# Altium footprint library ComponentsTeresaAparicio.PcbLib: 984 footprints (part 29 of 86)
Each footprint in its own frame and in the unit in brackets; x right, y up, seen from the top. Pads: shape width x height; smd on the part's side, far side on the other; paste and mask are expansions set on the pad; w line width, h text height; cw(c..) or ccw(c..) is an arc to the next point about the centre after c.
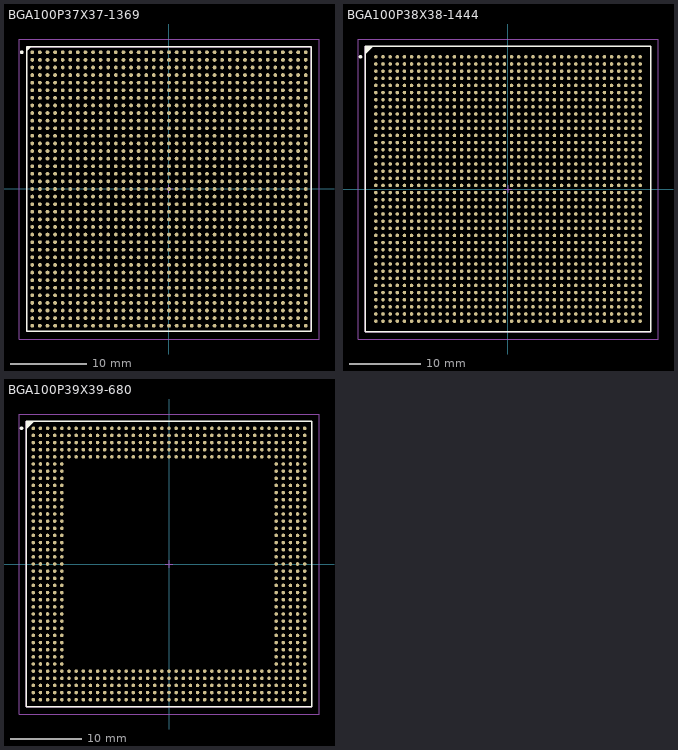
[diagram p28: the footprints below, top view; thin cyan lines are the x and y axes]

## BGA100P37X37-1369 [mm] "BGA, 1369-Leads, Body 37.5x37.5mm, Pitch 1mm"
height 3.5
pads (1369):
  round 0.5 smd: A1(-18,18) A2(-17,18) A3(-16,18) A4(-15,18) A5(-14,18) A6(-13,18) A7(-12,18) A8(-11,18) A9(-10,18) A10(-9,18) A11(-8,18) A12(-7,18) A13(-6,18) A14(-5,18) A15(-4,18) A16(-3,18) A17(-2,18) A18(-1,18) A19(0,18) A20(1,18) A21(2,18) A22(3,18) A23(4,18) A24(5,18) A25(6,18) A26(7,18) A27(8,18) A28(9,18) A29(10,18) A30(11,18) A31(12,18) A32(13,18) A33(14,18) A34(15,18) A35(16,18) A36(17,18) A37(18,18) AA1(-18,-2) AA2(-17,-2) AA3(-16,-2) AA4(-15,-2) AA5(-14,-2) AA6(-13,-2) AA7(-12,-2) AA8(-11,-2) AA9(-10,-2) AA10(-9,-2) AA11(-8,-2) AA12(-7,-2) AA13(-6,-2) AA14(-5,-2) AA15(-4,-2) AA16(-3,-2) AA17(-2,-2) AA18(-1,-2) AA19(0,-2) AA20(1,-2) AA21(2,-2) AA22(3,-2) AA23(4,-2) AA24(5,-2) AA25(6,-2) AA26(7,-2) AA27(8,-2) AA28(9,-2) AA29(10,-2) AA30(11,-2) AA31(12,-2) AA32(13,-2) AA33(14,-2) AA34(15,-2) AA35(16,-2) AA36(17,-2) AA37(18,-2) AB1(-18,-3) AB2(-17,-3) AB3(-16,-3) AB4(-15,-3) AB5(-14,-3) AB6(-13,-3) AB7(-12,-3) AB8(-11,-3) AB9(-10,-3) AB10(-9,-3) AB11(-8,-3) AB12(-7,-3) AB13(-6,-3) AB14(-5,-3) AB15(-4,-3) AB16(-3,-3) AB17(-2,-3) AB18(-1,-3) AB19(0,-3) AB20(1,-3) AB21(2,-3) AB22(3,-3) AB23(4,-3) AB24(5,-3) AB25(6,-3) AB26(7,-3) AB27(8,-3) AB28(9,-3) AB29(10,-3) AB30(11,-3) AB31(12,-3) AB32(13,-3) AB33(14,-3) AB34(15,-3) AB35(16,-3) AB36(17,-3) AB37(18,-3) AC1(-18,-4) AC2(-17,-4) AC3(-16,-4) AC4(-15,-4) AC5(-14,-4) AC6(-13,-4) AC7(-12,-4) AC8(-11,-4) AC9(-10,-4) AC10(-9,-4) AC11(-8,-4) AC12(-7,-4) AC13(-6,-4) AC14(-5,-4) AC15(-4,-4) AC16(-3,-4) AC17(-2,-4) AC18(-1,-4) AC19(0,-4) AC20(1,-4) AC21(2,-4) AC22(3,-4) AC23(4,-4) AC24(5,-4) AC25(6,-4) AC26(7,-4) AC27(8,-4) AC28(9,-4) AC29(10,-4) AC30(11,-4) AC31(12,-4) AC32(13,-4) AC33(14,-4) AC34(15,-4) AC35(16,-4) AC36(17,-4) AC37(18,-4) AD1(-18,-5) AD2(-17,-5) AD3(-16,-5) AD4(-15,-5) AD5(-14,-5) AD6(-13,-5) AD7(-12,-5) AD8(-11,-5) AD9(-10,-5) AD10(-9,-5) AD11(-8,-5) AD12(-7,-5) AD13(-6,-5) AD14(-5,-5) AD15(-4,-5) AD16(-3,-5) AD17(-2,-5) AD18(-1,-5) AD19(0,-5) AD20(1,-5) AD21(2,-5) AD22(3,-5) AD23(4,-5) AD24(5,-5) AD25(6,-5) AD26(7,-5) AD27(8,-5) AD28(9,-5) AD29(10,-5) AD30(11,-5) AD31(12,-5) AD32(13,-5) AD33(14,-5) AD34(15,-5) AD35(16,-5) AD36(17,-5) AD37(18,-5) AE1(-18,-6) AE2(-17,-6) AE3(-16,-6) AE4(-15,-6) AE5(-14,-6) AE6(-13,-6) AE7(-12,-6) AE8(-11,-6) AE9(-10,-6) AE10(-9,-6) AE11(-8,-6) AE12(-7,-6) AE13(-6,-6) AE14(-5,-6) AE15(-4,-6) AE16(-3,-6) AE17(-2,-6) AE18(-1,-6) AE19(0,-6) AE20(1,-6) AE21(2,-6) AE22(3,-6) AE23(4,-6) AE24(5,-6) AE25(6,-6) AE26(7,-6) AE27(8,-6) AE28(9,-6) AE29(10,-6) AE30(11,-6) AE31(12,-6) AE32(13,-6) AE33(14,-6) AE34(15,-6) AE35(16,-6) AE36(17,-6) AE37(18,-6) AF1(-18,-7) AF2(-17,-7) AF3(-16,-7) AF4(-15,-7) AF5(-14,-7) AF6(-13,-7) AF7(-12,-7) AF8(-11,-7) AF9(-10,-7) AF10(-9,-7) AF11(-8,-7) AF12(-7,-7) AF13(-6,-7) AF14(-5,-7) AF15(-4,-7) AF16(-3,-7) AF17(-2,-7) AF18(-1,-7) AF19(0,-7) AF20(1,-7) AF21(2,-7) AF22(3,-7) AF23(4,-7) AF24(5,-7) AF25(6,-7) AF26(7,-7) AF27(8,-7) AF28(9,-7) AF29(10,-7) AF30(11,-7) AF31(12,-7) AF32(13,-7) AF33(14,-7) AF34(15,-7) AF35(16,-7) AF36(17,-7) AF37(18,-7) AG1(-18,-8) AG2(-17,-8) AG3(-16,-8) AG4(-15,-8) AG5(-14,-8) AG6(-13,-8) AG7(-12,-8) AG8(-11,-8) AG9(-10,-8) AG10(-9,-8) AG11(-8,-8) AG12(-7,-8) AG13(-6,-8) AG14(-5,-8) AG15(-4,-8) AG16(-3,-8) AG17(-2,-8) AG18(-1,-8) AG19(0,-8) AG20(1,-8) AG21(2,-8) AG22(3,-8) AG23(4,-8) AG24(5,-8) AG25(6,-8) AG26(7,-8) AG27(8,-8) AG28(9,-8) AG29(10,-8) AG30(11,-8) AG31(12,-8) AG32(13,-8) AG33(14,-8) AG34(15,-8) AG35(16,-8) AG36(17,-8) AG37(18,-8) AH1(-18,-9) AH2(-17,-9) AH3(-16,-9) AH4(-15,-9) AH5(-14,-9) AH6(-13,-9) AH7(-12,-9) AH8(-11,-9) AH9(-10,-9) AH10(-9,-9) AH11(-8,-9) AH12(-7,-9) AH13(-6,-9) AH14(-5,-9) AH15(-4,-9) AH16(-3,-9) AH17(-2,-9) AH18(-1,-9) AH19(0,-9) AH20(1,-9) AH21(2,-9) AH22(3,-9) AH23(4,-9) AH24(5,-9) AH25(6,-9) AH26(7,-9) AH27(8,-9) AH28(9,-9) AH29(10,-9) AH30(11,-9) AH31(12,-9) AH32(13,-9) AH33(14,-9) AH34(15,-9) AH35(16,-9) AH36(17,-9) AH37(18,-9) AJ1(-18,-10) AJ2(-17,-10) AJ3(-16,-10) AJ4(-15,-10) AJ5(-14,-10) AJ6(-13,-10) AJ7(-12,-10) AJ8(-11,-10) AJ9(-10,-10) AJ10(-9,-10) AJ11(-8,-10) AJ12(-7,-10) AJ13(-6,-10) AJ14(-5,-10) AJ15(-4,-10) AJ16(-3,-10) AJ17(-2,-10) AJ18(-1,-10) AJ19(0,-10) AJ20(1,-10) AJ21(2,-10) AJ22(3,-10) AJ23(4,-10) AJ24(5,-10) AJ25(6,-10) AJ26(7,-10) AJ27(8,-10) AJ28(9,-10) AJ29(10,-10) AJ30(11,-10) AJ31(12,-10) AJ32(13,-10) AJ33(14,-10) AJ34(15,-10) AJ35(16,-10) AJ36(17,-10) AJ37(18,-10) AK1(-18,-11) AK2(-17,-11) AK3(-16,-11) AK4(-15,-11) AK5(-14,-11) AK6(-13,-11) AK7(-12,-11) AK8(-11,-11) AK9(-10,-11) AK10(-9,-11) AK11(-8,-11) AK12(-7,-11) AK13(-6,-11) AK14(-5,-11) AK15(-4,-11) AK16(-3,-11) AK17(-2,-11) AK18(-1,-11) AK19(0,-11) AK20(1,-11) AK21(2,-11) AK22(3,-11) AK23(4,-11) AK24(5,-11) AK25(6,-11) AK26(7,-11) AK27(8,-11) AK28(9,-11) AK29(10,-11) AK30(11,-11) AK31(12,-11) AK32(13,-11) AK33(14,-11) AK34(15,-11) AK35(16,-11) AK36(17,-11) AK37(18,-11) AL1(-18,-12) AL2(-17,-12) AL3(-16,-12) AL4(-15,-12) AL5(-14,-12) AL6(-13,-12) AL7(-12,-12) AL8(-11,-12) AL9(-10,-12) AL10(-9,-12) AL11(-8,-12) AL12(-7,-12) AL13(-6,-12) AL14(-5,-12) AL15(-4,-12) AL16(-3,-12) AL17(-2,-12) AL18(-1,-12) AL19(0,-12) AL20(1,-12) AL21(2,-12) AL22(3,-12) AL23(4,-12) AL24(5,-12) AL25(6,-12) AL26(7,-12) AL27(8,-12) AL28(9,-12) AL29(10,-12) AL30(11,-12) AL31(12,-12) AL32(13,-12) AL33(14,-12) AL34(15,-12) AL35(16,-12) AL36(17,-12) AL37(18,-12) AM1(-18,-13) AM2(-17,-13) AM3(-16,-13) AM4(-15,-13) AM5(-14,-13) AM6(-13,-13) AM7(-12,-13) AM8(-11,-13) AM9(-10,-13) AM10(-9,-13) AM11(-8,-13) AM12(-7,-13) AM13(-6,-13) AM14(-5,-13) AM15(-4,-13) AM16(-3,-13) AM17(-2,-13) AM18(-1,-13) AM19(0,-13) AM20(1,-13) AM21(2,-13) AM22(3,-13) AM23(4,-13) AM24(5,-13) AM25(6,-13) AM26(7,-13) AM27(8,-13) AM28(9,-13) AM29(10,-13) AM30(11,-13) AM31(12,-13) AM32(13,-13) AM33(14,-13) AM34(15,-13) AM35(16,-13) AM36(17,-13) AM37(18,-13) AN1(-18,-14) AN2(-17,-14) AN3(-16,-14) AN4(-15,-14) AN5(-14,-14) AN6(-13,-14) AN7(-12,-14) AN8(-11,-14) AN9(-10,-14) AN10(-9,-14) AN11(-8,-14) AN12(-7,-14) AN13(-6,-14) AN14(-5,-14) AN15(-4,-14) AN16(-3,-14) AN17(-2,-14) AN18(-1,-14) AN19(0,-14) AN20(1,-14) AN21(2,-14) AN22(3,-14) AN23(4,-14) AN24(5,-14) AN25(6,-14) AN26(7,-14) AN27(8,-14) AN28(9,-14) AN29(10,-14) AN30(11,-14) AN31(12,-14) AN32(13,-14) AN33(14,-14) AN34(15,-14) AN35(16,-14) AN36(17,-14) AN37(18,-14) AP1(-18,-15) AP2(-17,-15) AP3(-16,-15) AP4(-15,-15) AP5(-14,-15) AP6(-13,-15) AP7(-12,-15) AP8(-11,-15) AP9(-10,-15) AP10(-9,-15) AP11(-8,-15) AP12(-7,-15) AP13(-6,-15) AP14(-5,-15) AP15(-4,-15) AP16(-3,-15) AP17(-2,-15) AP18(-1,-15) AP19(0,-15) AP20(1,-15) AP21(2,-15) AP22(3,-15) AP23(4,-15) AP24(5,-15) AP25(6,-15) AP26(7,-15) AP27(8,-15) AP28(9,-15) AP29(10,-15) AP30(11,-15) AP31(12,-15) AP32(13,-15) AP33(14,-15) AP34(15,-15) AP35(16,-15) AP36(17,-15) AP37(18,-15) AR1(-18,-16) AR2(-17,-16) AR3(-16,-16) AR4(-15,-16) AR5(-14,-16) AR6(-13,-16) AR7(-12,-16) AR8(-11,-16) AR9(-10,-16) AR10(-9,-16) AR11(-8,-16) AR12(-7,-16) AR13(-6,-16) AR14(-5,-16) AR15(-4,-16) AR16(-3,-16) AR17(-2,-16) AR18(-1,-16) AR19(0,-16) AR20(1,-16) AR21(2,-16) AR22(3,-16) AR23(4,-16) AR24(5,-16) AR25(6,-16) AR26(7,-16) AR27(8,-16) AR28(9,-16) AR29(10,-16) AR30(11,-16) AR31(12,-16) AR32(13,-16) AR33(14,-16) AR34(15,-16) AR35(16,-16) AR36(17,-16) AR37(18,-16) AT1(-18,-17) AT2(-17,-17) AT3(-16,-17) AT4(-15,-17) AT5(-14,-17) AT6(-13,-17) AT7(-12,-17) AT8(-11,-17) AT9(-10,-17) AT10(-9,-17) AT11(-8,-17) AT12(-7,-17) AT13(-6,-17) AT14(-5,-17) AT15(-4,-17) AT16(-3,-17) AT17(-2,-17) AT18(-1,-17) AT19(0,-17) AT20(1,-17) AT21(2,-17) AT22(3,-17) AT23(4,-17) AT24(5,-17) AT25(6,-17) AT26(7,-17) AT27(8,-17) AT28(9,-17) AT29(10,-17) AT30(11,-17) AT31(12,-17) AT32(13,-17) AT33(14,-17) AT34(15,-17) AT35(16,-17) AT36(17,-17) AT37(18,-17) AU1(-18,-18) AU2(-17,-18) AU3(-16,-18) AU4(-15,-18) AU5(-14,-18) AU6(-13,-18) AU7(-12,-18) AU8(-11,-18) AU9(-10,-18) AU10(-9,-18) AU11(-8,-18) AU12(-7,-18) AU13(-6,-18) AU14(-5,-18) AU15(-4,-18) AU16(-3,-18) AU17(-2,-18) AU18(-1,-18) AU19(0,-18) AU20(1,-18) AU21(2,-18) AU22(3,-18) AU23(4,-18) AU24(5,-18) AU25(6,-18) AU26(7,-18) AU27(8,-18) AU28(9,-18) AU29(10,-18) AU30(11,-18) AU31(12,-18) AU32(13,-18) AU33(14,-18) AU34(15,-18) AU35(16,-18) AU36(17,-18) AU37(18,-18) B1(-18,17) B2(-17,17) B3(-16,17) B4(-15,17) B5(-14,17) B6(-13,17) B7(-12,17) B8(-11,17) B9(-10,17) B10(-9,17) B11(-8,17) B12(-7,17) B13(-6,17) B14(-5,17) B15(-4,17) B16(-3,17) B17(-2,17) B18(-1,17) B19(0,17) B20(1,17) B21(2,17) B22(3,17) B23(4,17) B24(5,17) B25(6,17) B26(7,17) B27(8,17) B28(9,17) B29(10,17) B30(11,17) B31(12,17) B32(13,17) B33(14,17) B34(15,17) B35(16,17) B36(17,17) B37(18,17) C1(-18,16) C2(-17,16) C3(-16,16) C4(-15,16) C5(-14,16) C6(-13,16) C7(-12,16) C8(-11,16) C9(-10,16) C10(-9,16) C11(-8,16) C12(-7,16) C13(-6,16) C14(-5,16) C15(-4,16) C16(-3,16) C17(-2,16) C18(-1,16) C19(0,16) C20(1,16) C21(2,16) C22(3,16) C23(4,16) C24(5,16) C25(6,16) C26(7,16) C27(8,16) C28(9,16) C29(10,16) C30(11,16) C31(12,16) C32(13,16) C33(14,16) C34(15,16) C35(16,16) C36(17,16) C37(18,16) D1(-18,15) D2(-17,15) D3(-16,15) D4(-15,15) D5(-14,15) D6(-13,15) D7(-12,15) D8(-11,15) D9(-10,15) D10(-9,15) D11(-8,15) D12(-7,15) D13(-6,15) D14(-5,15) D15(-4,15) D16(-3,15) D17(-2,15) D18(-1,15) D19(0,15) D20(1,15) D21(2,15) D22(3,15) D23(4,15) D24(5,15) D25(6,15) D26(7,15) D27(8,15) D28(9,15) D29(10,15) D30(11,15) D31(12,15) D32(13,15) D33(14,15) D34(15,15) D35(16,15) D36(17,15) D37(18,15) E1(-18,14) E2(-17,14) E3(-16,14) E4(-15,14) E5(-14,14) E6(-13,14) E7(-12,14) E8(-11,14) E9(-10,14) E10(-9,14) E11(-8,14) E12(-7,14) E13(-6,14) E14(-5,14) E15(-4,14) E16(-3,14) E17(-2,14) E18(-1,14) E19(0,14) E20(1,14) E21(2,14) E22(3,14) E23(4,14) E24(5,14) E25(6,14) E26(7,14) E27(8,14) E28(9,14) E29(10,14) E30(11,14) E31(12,14) E32(13,14) E33(14,14) E34(15,14) E35(16,14) E36(17,14) E37(18,14) F1(-18,13) F2(-17,13) F3(-16,13) F4(-15,13) F5(-14,13) F6(-13,13) F7(-12,13) F8(-11,13) F9(-10,13) F10(-9,13) F11(-8,13) F12(-7,13) F13(-6,13) F14(-5,13) F15(-4,13) F16(-3,13) F17(-2,13) F18(-1,13) F19(0,13) F20(1,13) F21(2,13) F22(3,13) F23(4,13) F24(5,13) F25(6,13) F26(7,13) F27(8,13) F28(9,13) F29(10,13) F30(11,13) F31(12,13) F32(13,13) F33(14,13) F34(15,13) F35(16,13) F36(17,13) F37(18,13) G1(-18,12) G2(-17,12) G3(-16,12) G4(-15,12) G5(-14,12) G6(-13,12) G7(-12,12) G8(-11,12) G9(-10,12) G10(-9,12) G11(-8,12) G12(-7,12) G13(-6,12) G14(-5,12) G15(-4,12) G16(-3,12) G17(-2,12) G18(-1,12) G19(0,12) G20(1,12) G21(2,12) G22(3,12) G23(4,12) G24(5,12) G25(6,12) G26(7,12) G27(8,12) G28(9,12) G29(10,12) G30(11,12) G31(12,12) G32(13,12) G33(14,12) G34(15,12) G35(16,12) G36(17,12) G37(18,12) H1(-18,11) H2(-17,11) H3(-16,11) H4(-15,11) H5(-14,11) H6(-13,11) H7(-12,11) H8(-11,11) H9(-10,11) H10(-9,11) H11(-8,11) H12(-7,11) H13(-6,11) H14(-5,11) H15(-4,11) H16(-3,11) H17(-2,11) H18(-1,11) H19(0,11) H20(1,11) H21(2,11) H22(3,11) H23(4,11) H24(5,11) H25(6,11) H26(7,11) H27(8,11) H28(9,11) H29(10,11) H30(11,11) H31(12,11) H32(13,11) H33(14,11) H34(15,11) H35(16,11) H36(17,11) H37(18,11) J1(-18,10) J2(-17,10) J3(-16,10) J4(-15,10) J5(-14,10) J6(-13,10) J7(-12,10) J8(-11,10) J9(-10,10) J10(-9,10) J11(-8,10) J12(-7,10) J13(-6,10) J14(-5,10) J15(-4,10) J16(-3,10) J17(-2,10) J18(-1,10) J19(0,10) J20(1,10) J21(2,10) J22(3,10) J23(4,10) J24(5,10) J25(6,10) J26(7,10) J27(8,10) J28(9,10) J29(10,10) J30(11,10) J31(12,10) J32(13,10) J33(14,10) J34(15,10) J35(16,10) J36(17,10) J37(18,10) K1(-18,9) K2(-17,9) K3(-16,9) K4(-15,9) K5(-14,9) K6(-13,9) K7(-12,9) K8(-11,9) K9(-10,9) K10(-9,9) K11(-8,9) K12(-7,9) K13(-6,9) K14(-5,9) K15(-4,9) K16(-3,9) K17(-2,9) K18(-1,9) K19(0,9) K20(1,9) K21(2,9) K22(3,9) K23(4,9) K24(5,9) K25(6,9) K26(7,9) K27(8,9) K28(9,9) K29(10,9) K30(11,9) K31(12,9) K32(13,9) K33(14,9) K34(15,9) K35(16,9) K36(17,9) K37(18,9) L1(-18,8) L2(-17,8) L3(-16,8) L4(-15,8) L5(-14,8) L6(-13,8) L7(-12,8) L8(-11,8) L9(-10,8) L10(-9,8) L11(-8,8) L12(-7,8) L13(-6,8) L14(-5,8) L15(-4,8) L16(-3,8) L17(-2,8) L18(-1,8) L19(0,8) L20(1,8) L21(2,8) L22(3,8) L23(4,8) L24(5,8) L25(6,8) L26(7,8) L27(8,8) L28(9,8) L29(10,8) L30(11,8) L31(12,8) L32(13,8) L33(14,8) L34(15,8) L35(16,8) L36(17,8) L37(18,8) M1(-18,7) M2(-17,7) M3(-16,7) M4(-15,7) M5(-14,7) M6(-13,7) M7(-12,7) M8(-11,7) M9(-10,7) M10(-9,7) M11(-8,7) M12(-7,7) M13(-6,7) M14(-5,7) M15(-4,7) M16(-3,7) M17(-2,7) M18(-1,7) M19(0,7) M20(1,7) M21(2,7) M22(3,7) M23(4,7) M24(5,7) M25(6,7) M26(7,7) M27(8,7) M28(9,7) M29(10,7) M30(11,7) M31(12,7) M32(13,7) M33(14,7) M34(15,7) M35(16,7) M36(17,7) M37(18,7) N1(-18,6) N2(-17,6) N3(-16,6) N4(-15,6) N5(-14,6) N6(-13,6) N7(-12,6) N8(-11,6) N9(-10,6) N10(-9,6) N11(-8,6) N12(-7,6) N13(-6,6) N14(-5,6) N15(-4,6) N16(-3,6) N17(-2,6) N18(-1,6) N19(0,6) N20(1,6) N21(2,6) N22(3,6) N23(4,6) N24(5,6) N25(6,6) N26(7,6) N27(8,6) N28(9,6) N29(10,6) N30(11,6) N31(12,6) N32(13,6) N33(14,6) N34(15,6) N35(16,6) N36(17,6) N37(18,6) P1(-18,5) P2(-17,5) P3(-16,5) P4(-15,5) P5(-14,5) P6(-13,5) P7(-12,5) P8(-11,5) P9(-10,5) P10(-9,5) P11(-8,5) P12(-7,5) P13(-6,5) P14(-5,5) P15(-4,5) P16(-3,5) P17(-2,5) P18(-1,5) P19(0,5) P20(1,5) P21(2,5) P22(3,5) P23(4,5) P24(5,5) P25(6,5) P26(7,5) P27(8,5) P28(9,5) P29(10,5) P30(11,5) P31(12,5) P32(13,5) P33(14,5) P34(15,5) P35(16,5) P36(17,5) P37(18,5) R1(-18,4) R2(-17,4) R3(-16,4) R4(-15,4) R5(-14,4) R6(-13,4) R7(-12,4) R8(-11,4) R9(-10,4) R10(-9,4) R11(-8,4) R12(-7,4) R13(-6,4) R14(-5,4) R15(-4,4) R16(-3,4) R17(-2,4) R18(-1,4) R19(0,4) R20(1,4) R21(2,4) R22(3,4) R23(4,4) R24(5,4) R25(6,4) R26(7,4) R27(8,4) R28(9,4) R29(10,4) R30(11,4) R31(12,4) R32(13,4) R33(14,4) R34(15,4) R35(16,4) R36(17,4) R37(18,4) T1(-18,3) T2(-17,3) T3(-16,3) T4(-15,3) T5(-14,3) T6(-13,3) T7(-12,3) T8(-11,3) T9(-10,3) T10(-9,3) T11(-8,3) T12(-7,3) T13(-6,3) T14(-5,3) T15(-4,3) T16(-3,3) T17(-2,3) T18(-1,3) T19(0,3) T20(1,3) T21(2,3) T22(3,3) T23(4,3) T24(5,3) T25(6,3) T26(7,3) T27(8,3) T28(9,3) T29(10,3) T30(11,3) T31(12,3) T32(13,3) T33(14,3) T34(15,3) T35(16,3) T36(17,3) T37(18,3) U1(-18,2) U2(-17,2) U3(-16,2) U4(-15,2) U5(-14,2) U6(-13,2) U7(-12,2) U8(-11,2) U9(-10,2) U10(-9,2) U11(-8,2) U12(-7,2) U13(-6,2) U14(-5,2) U15(-4,2) U16(-3,2) U17(-2,2) U18(-1,2) U19(0,2) U20(1,2) U21(2,2) U22(3,2) U23(4,2) U24(5,2) U25(6,2) U26(7,2) U27(8,2) U28(9,2) U29(10,2) U30(11,2) U31(12,2) U32(13,2) U33(14,2) U34(15,2) U35(16,2) U36(17,2) U37(18,2) V1(-18,1) V2(-17,1) V3(-16,1) V4(-15,1) V5(-14,1) V6(-13,1) V7(-12,1) V8(-11,1) V9(-10,1) V10(-9,1) V11(-8,1) V12(-7,1) V13(-6,1) V14(-5,1) V15(-4,1) V16(-3,1) V17(-2,1) V18(-1,1) V19(0,1) V20(1,1) V21(2,1) V22(3,1) V23(4,1) V24(5,1) V25(6,1) V26(7,1) V27(8,1) V28(9,1) V29(10,1) V30(11,1) V31(12,1) V32(13,1) V33(14,1) V34(15,1) V35(16,1) V36(17,1) V37(18,1) W1(-18,0) W2(-17,0) W3(-16,0) W4(-15,0) W5(-14,0) W6(-13,0) W7(-12,0) W8(-11,0) W9(-10,0) W10(-9,0) W11(-8,0) W12(-7,0) W13(-6,0) W14(-5,0) W15(-4,0) W16(-3,0) W17(-2,0) W18(-1,0) W19(0,0) W20(1,0) W21(2,0) W22(3,0) W23(4,0) W24(5,0) W25(6,0) W26(7,0) W27(8,0) W28(9,0) W29(10,0) W30(11,0) W31(12,0) W32(13,0) W33(14,0) W34(15,0) W35(16,0) W36(17,0) W37(18,0) Y1(-18,-1) Y2(-17,-1) Y3(-16,-1) Y4(-15,-1) Y5(-14,-1) Y6(-13,-1) Y7(-12,-1) Y8(-11,-1) Y9(-10,-1) Y10(-9,-1) Y11(-8,-1) Y12(-7,-1) Y13(-6,-1) Y14(-5,-1) Y15(-4,-1) Y16(-3,-1) Y17(-2,-1) Y18(-1,-1) Y19(0,-1) Y20(1,-1) Y21(2,-1) Y22(3,-1) Y23(4,-1) Y24(5,-1) Y25(6,-1) Y26(7,-1) Y27(8,-1) Y28(9,-1) Y29(10,-1) Y30(11,-1) Y31(12,-1) Y32(13,-1) Y33(14,-1) Y34(15,-1) Y35(16,-1) Y36(17,-1) Y37(18,-1)
Top Overlay:
  circle w0.25: c-19.4,18 r0.125
  region: -18.169,18.75 -18.75,18.169 -18.75,18.75
  lines w0.2: -18.75,18.169 -18.169,18.75 ; -18.75,-18.75 -18.75,18.75 18.75,18.75 18.75,-18.75 -18.75,-18.75
Mechanical 13:
  lines w0.1: -18.75,-18.75 -18.75,18.75 18.75,18.75 18.75,-18.75 -18.75,-18.75
Mechanical 15:
  lines w0.1: -0.5,0 0.5,0 ; 0,-0.5 0,0.5 ; -19.75,-19.75 -19.75,19.75 19.75,19.75 19.75,-19.75 -19.75,-19.75
3D body: height 0, standoff 0, extent -18.75,-18.75 18.75,18.75

## BGA100P38X38-1444 [mm] "BGA, 1444-Leads, Body 40x40mm, Pitch 1mm"
height 3.5
pads (1444):
  round 0.5 smd: A1(-18.5,18.5) A2(-17.5,18.5) A3(-16.5,18.5) A4(-15.5,18.5) A5(-14.5,18.5) A6(-13.5,18.5) A7(-12.5,18.5) A8(-11.5,18.5) A9(-10.5,18.5) A10(-9.5,18.5) A11(-8.5,18.5) A12(-7.5,18.5) A13(-6.5,18.5) A14(-5.5,18.5) A15(-4.5,18.5) A16(-3.5,18.5) A17(-2.5,18.5) A18(-1.5,18.5) A19(-0.5,18.5) A20(0.5,18.5) A21(1.5,18.5) A22(2.5,18.5) A23(3.5,18.5) A24(4.5,18.5) A25(5.5,18.5) A26(6.5,18.5) A27(7.5,18.5) A28(8.5,18.5) A29(9.5,18.5) A30(10.5,18.5) A31(11.5,18.5) A32(12.5,18.5) A33(13.5,18.5) A34(14.5,18.5) A35(15.5,18.5) A36(16.5,18.5) A37(17.5,18.5) A38(18.5,18.5) AA1(-18.5,-1.5) AA2(-17.5,-1.5) AA3(-16.5,-1.5) AA4(-15.5,-1.5) AA5(-14.5,-1.5) AA6(-13.5,-1.5) AA7(-12.5,-1.5) AA8(-11.5,-1.5) AA9(-10.5,-1.5) AA10(-9.5,-1.5) AA11(-8.5,-1.5) AA12(-7.5,-1.5) AA13(-6.5,-1.5) AA14(-5.5,-1.5) AA15(-4.5,-1.5) AA16(-3.5,-1.5) AA17(-2.5,-1.5) AA18(-1.5,-1.5) AA19(-0.5,-1.5) AA20(0.5,-1.5) AA21(1.5,-1.5) AA22(2.5,-1.5) AA23(3.5,-1.5) AA24(4.5,-1.5) AA25(5.5,-1.5) AA26(6.5,-1.5) AA27(7.5,-1.5) AA28(8.5,-1.5) AA29(9.5,-1.5) AA30(10.5,-1.5) AA31(11.5,-1.5) AA32(12.5,-1.5) AA33(13.5,-1.5) AA34(14.5,-1.5) AA35(15.5,-1.5) AA36(16.5,-1.5) AA37(17.5,-1.5) AA38(18.5,-1.5) AB1(-18.5,-2.5) AB2(-17.5,-2.5) AB3(-16.5,-2.5) AB4(-15.5,-2.5) AB5(-14.5,-2.5) AB6(-13.5,-2.5) AB7(-12.5,-2.5) AB8(-11.5,-2.5) AB9(-10.5,-2.5) AB10(-9.5,-2.5) AB11(-8.5,-2.5) AB12(-7.5,-2.5) AB13(-6.5,-2.5) AB14(-5.5,-2.5) AB15(-4.5,-2.5) AB16(-3.5,-2.5) AB17(-2.5,-2.5) AB18(-1.5,-2.5) AB19(-0.5,-2.5) AB20(0.5,-2.5) AB21(1.5,-2.5) AB22(2.5,-2.5) AB23(3.5,-2.5) AB24(4.5,-2.5) AB25(5.5,-2.5) AB26(6.5,-2.5) AB27(7.5,-2.5) AB28(8.5,-2.5) AB29(9.5,-2.5) AB30(10.5,-2.5) AB31(11.5,-2.5) AB32(12.5,-2.5) AB33(13.5,-2.5) AB34(14.5,-2.5) AB35(15.5,-2.5) AB36(16.5,-2.5) AB37(17.5,-2.5) AB38(18.5,-2.5) AC1(-18.5,-3.5) AC2(-17.5,-3.5) AC3(-16.5,-3.5) AC4(-15.5,-3.5) AC5(-14.5,-3.5) AC6(-13.5,-3.5) AC7(-12.5,-3.5) AC8(-11.5,-3.5) AC9(-10.5,-3.5) AC10(-9.5,-3.5) AC11(-8.5,-3.5) AC12(-7.5,-3.5) AC13(-6.5,-3.5) AC14(-5.5,-3.5) AC15(-4.5,-3.5) AC16(-3.5,-3.5) AC17(-2.5,-3.5) AC18(-1.5,-3.5) AC19(-0.5,-3.5) AC20(0.5,-3.5) AC21(1.5,-3.5) AC22(2.5,-3.5) AC23(3.5,-3.5) AC24(4.5,-3.5) AC25(5.5,-3.5) AC26(6.5,-3.5) AC27(7.5,-3.5) AC28(8.5,-3.5) AC29(9.5,-3.5) AC30(10.5,-3.5) AC31(11.5,-3.5) AC32(12.5,-3.5) AC33(13.5,-3.5) AC34(14.5,-3.5) AC35(15.5,-3.5) AC36(16.5,-3.5) AC37(17.5,-3.5) AC38(18.5,-3.5) AD1(-18.5,-4.5) AD2(-17.5,-4.5) AD3(-16.5,-4.5) AD4(-15.5,-4.5) AD5(-14.5,-4.5) AD6(-13.5,-4.5) AD7(-12.5,-4.5) AD8(-11.5,-4.5) AD9(-10.5,-4.5) AD10(-9.5,-4.5) AD11(-8.5,-4.5) AD12(-7.5,-4.5) AD13(-6.5,-4.5) AD14(-5.5,-4.5) AD15(-4.5,-4.5) AD16(-3.5,-4.5) AD17(-2.5,-4.5) AD18(-1.5,-4.5) AD19(-0.5,-4.5) AD20(0.5,-4.5) AD21(1.5,-4.5) AD22(2.5,-4.5) AD23(3.5,-4.5) AD24(4.5,-4.5) AD25(5.5,-4.5) AD26(6.5,-4.5) AD27(7.5,-4.5) AD28(8.5,-4.5) AD29(9.5,-4.5) AD30(10.5,-4.5) AD31(11.5,-4.5) AD32(12.5,-4.5) AD33(13.5,-4.5) AD34(14.5,-4.5) AD35(15.5,-4.5) AD36(16.5,-4.5) AD37(17.5,-4.5) AD38(18.5,-4.5) AE1(-18.5,-5.5) AE2(-17.5,-5.5) AE3(-16.5,-5.5) AE4(-15.5,-5.5) AE5(-14.5,-5.5) AE6(-13.5,-5.5) AE7(-12.5,-5.5) AE8(-11.5,-5.5) AE9(-10.5,-5.5) AE10(-9.5,-5.5) AE11(-8.5,-5.5) AE12(-7.5,-5.5) AE13(-6.5,-5.5) AE14(-5.5,-5.5) AE15(-4.5,-5.5) AE16(-3.5,-5.5) AE17(-2.5,-5.5) AE18(-1.5,-5.5) AE19(-0.5,-5.5) AE20(0.5,-5.5) AE21(1.5,-5.5) AE22(2.5,-5.5) AE23(3.5,-5.5) AE24(4.5,-5.5) AE25(5.5,-5.5) AE26(6.5,-5.5) AE27(7.5,-5.5) AE28(8.5,-5.5) AE29(9.5,-5.5) AE30(10.5,-5.5) AE31(11.5,-5.5) AE32(12.5,-5.5) AE33(13.5,-5.5) AE34(14.5,-5.5) AE35(15.5,-5.5) AE36(16.5,-5.5) AE37(17.5,-5.5) AE38(18.5,-5.5) AF1(-18.5,-6.5) AF2(-17.5,-6.5) AF3(-16.5,-6.5) AF4(-15.5,-6.5) AF5(-14.5,-6.5) AF6(-13.5,-6.5) AF7(-12.5,-6.5) AF8(-11.5,-6.5) AF9(-10.5,-6.5) AF10(-9.5,-6.5) AF11(-8.5,-6.5) AF12(-7.5,-6.5) AF13(-6.5,-6.5) AF14(-5.5,-6.5) AF15(-4.5,-6.5) AF16(-3.5,-6.5) AF17(-2.5,-6.5) AF18(-1.5,-6.5) AF19(-0.5,-6.5) AF20(0.5,-6.5) AF21(1.5,-6.5) AF22(2.5,-6.5) AF23(3.5,-6.5) AF24(4.5,-6.5) AF25(5.5,-6.5) AF26(6.5,-6.5) AF27(7.5,-6.5) AF28(8.5,-6.5) AF29(9.5,-6.5) AF30(10.5,-6.5) AF31(11.5,-6.5) AF32(12.5,-6.5) AF33(13.5,-6.5) AF34(14.5,-6.5) AF35(15.5,-6.5) AF36(16.5,-6.5) AF37(17.5,-6.5) AF38(18.5,-6.5) AG1(-18.5,-7.5) AG2(-17.5,-7.5) AG3(-16.5,-7.5) AG4(-15.5,-7.5) AG5(-14.5,-7.5) AG6(-13.5,-7.5) AG7(-12.5,-7.5) AG8(-11.5,-7.5) AG9(-10.5,-7.5) AG10(-9.5,-7.5) AG11(-8.5,-7.5) AG12(-7.5,-7.5) AG13(-6.5,-7.5) AG14(-5.5,-7.5) AG15(-4.5,-7.5) AG16(-3.5,-7.5) AG17(-2.5,-7.5) AG18(-1.5,-7.5) AG19(-0.5,-7.5) AG20(0.5,-7.5) AG21(1.5,-7.5) AG22(2.5,-7.5) AG23(3.5,-7.5) AG24(4.5,-7.5) AG25(5.5,-7.5) AG26(6.5,-7.5) AG27(7.5,-7.5) AG28(8.5,-7.5) AG29(9.5,-7.5) AG30(10.5,-7.5) AG31(11.5,-7.5) AG32(12.5,-7.5) AG33(13.5,-7.5) AG34(14.5,-7.5) AG35(15.5,-7.5) AG36(16.5,-7.5) AG37(17.5,-7.5) AG38(18.5,-7.5) AH1(-18.5,-8.5) AH2(-17.5,-8.5) AH3(-16.5,-8.5) AH4(-15.5,-8.5) AH5(-14.5,-8.5) AH6(-13.5,-8.5) AH7(-12.5,-8.5) AH8(-11.5,-8.5) AH9(-10.5,-8.5) AH10(-9.5,-8.5) AH11(-8.5,-8.5) AH12(-7.5,-8.5) AH13(-6.5,-8.5) AH14(-5.5,-8.5) AH15(-4.5,-8.5) AH16(-3.5,-8.5) AH17(-2.5,-8.5) AH18(-1.5,-8.5) AH19(-0.5,-8.5) AH20(0.5,-8.5) AH21(1.5,-8.5) AH22(2.5,-8.5) AH23(3.5,-8.5) AH24(4.5,-8.5) AH25(5.5,-8.5) AH26(6.5,-8.5) AH27(7.5,-8.5) AH28(8.5,-8.5) AH29(9.5,-8.5) AH30(10.5,-8.5) AH31(11.5,-8.5) AH32(12.5,-8.5) AH33(13.5,-8.5) AH34(14.5,-8.5) AH35(15.5,-8.5) AH36(16.5,-8.5) AH37(17.5,-8.5) AH38(18.5,-8.5) AJ1(-18.5,-9.5) AJ2(-17.5,-9.5) AJ3(-16.5,-9.5) AJ4(-15.5,-9.5) AJ5(-14.5,-9.5) AJ6(-13.5,-9.5) AJ7(-12.5,-9.5) AJ8(-11.5,-9.5) AJ9(-10.5,-9.5) AJ10(-9.5,-9.5) AJ11(-8.5,-9.5) AJ12(-7.5,-9.5) AJ13(-6.5,-9.5) AJ14(-5.5,-9.5) AJ15(-4.5,-9.5) AJ16(-3.5,-9.5) AJ17(-2.5,-9.5) AJ18(-1.5,-9.5) AJ19(-0.5,-9.5) AJ20(0.5,-9.5) AJ21(1.5,-9.5) AJ22(2.5,-9.5) AJ23(3.5,-9.5) AJ24(4.5,-9.5) AJ25(5.5,-9.5) AJ26(6.5,-9.5) AJ27(7.5,-9.5) AJ28(8.5,-9.5) AJ29(9.5,-9.5) AJ30(10.5,-9.5) AJ31(11.5,-9.5) AJ32(12.5,-9.5) AJ33(13.5,-9.5) AJ34(14.5,-9.5) AJ35(15.5,-9.5) AJ36(16.5,-9.5) AJ37(17.5,-9.5) AJ38(18.5,-9.5) AK1(-18.5,-10.5) AK2(-17.5,-10.5) AK3(-16.5,-10.5) AK4(-15.5,-10.5) AK5(-14.5,-10.5) AK6(-13.5,-10.5) AK7(-12.5,-10.5) AK8(-11.5,-10.5) AK9(-10.5,-10.5) AK10(-9.5,-10.5) AK11(-8.5,-10.5) AK12(-7.5,-10.5) AK13(-6.5,-10.5) AK14(-5.5,-10.5) AK15(-4.5,-10.5) AK16(-3.5,-10.5) AK17(-2.5,-10.5) AK18(-1.5,-10.5) AK19(-0.5,-10.5) AK20(0.5,-10.5) AK21(1.5,-10.5) AK22(2.5,-10.5) AK23(3.5,-10.5) AK24(4.5,-10.5) AK25(5.5,-10.5) AK26(6.5,-10.5) AK27(7.5,-10.5) AK28(8.5,-10.5) AK29(9.5,-10.5) AK30(10.5,-10.5) AK31(11.5,-10.5) AK32(12.5,-10.5) AK33(13.5,-10.5) AK34(14.5,-10.5) AK35(15.5,-10.5) AK36(16.5,-10.5) AK37(17.5,-10.5) AK38(18.5,-10.5) AL1(-18.5,-11.5) AL2(-17.5,-11.5) AL3(-16.5,-11.5) AL4(-15.5,-11.5) AL5(-14.5,-11.5) AL6(-13.5,-11.5) AL7(-12.5,-11.5) AL8(-11.5,-11.5) AL9(-10.5,-11.5) AL10(-9.5,-11.5) AL11(-8.5,-11.5) AL12(-7.5,-11.5) AL13(-6.5,-11.5) AL14(-5.5,-11.5) AL15(-4.5,-11.5) AL16(-3.5,-11.5) AL17(-2.5,-11.5) AL18(-1.5,-11.5) AL19(-0.5,-11.5) AL20(0.5,-11.5) AL21(1.5,-11.5) AL22(2.5,-11.5) AL23(3.5,-11.5) AL24(4.5,-11.5) AL25(5.5,-11.5) AL26(6.5,-11.5) AL27(7.5,-11.5) AL28(8.5,-11.5) AL29(9.5,-11.5) AL30(10.5,-11.5) AL31(11.5,-11.5) AL32(12.5,-11.5) AL33(13.5,-11.5) AL34(14.5,-11.5) AL35(15.5,-11.5) AL36(16.5,-11.5) AL37(17.5,-11.5) AL38(18.5,-11.5) AM1(-18.5,-12.5) AM2(-17.5,-12.5) AM3(-16.5,-12.5) AM4(-15.5,-12.5) AM5(-14.5,-12.5) AM6(-13.5,-12.5) AM7(-12.5,-12.5) AM8(-11.5,-12.5) AM9(-10.5,-12.5) AM10(-9.5,-12.5) AM11(-8.5,-12.5) AM12(-7.5,-12.5) AM13(-6.5,-12.5) AM14(-5.5,-12.5) AM15(-4.5,-12.5) AM16(-3.5,-12.5) AM17(-2.5,-12.5) AM18(-1.5,-12.5) AM19(-0.5,-12.5) AM20(0.5,-12.5) AM21(1.5,-12.5) AM22(2.5,-12.5) AM23(3.5,-12.5) AM24(4.5,-12.5) AM25(5.5,-12.5) AM26(6.5,-12.5) AM27(7.5,-12.5) AM28(8.5,-12.5) AM29(9.5,-12.5) AM30(10.5,-12.5) AM31(11.5,-12.5) AM32(12.5,-12.5) AM33(13.5,-12.5) AM34(14.5,-12.5) AM35(15.5,-12.5) AM36(16.5,-12.5) AM37(17.5,-12.5) AM38(18.5,-12.5) AN1(-18.5,-13.5) AN2(-17.5,-13.5) AN3(-16.5,-13.5) AN4(-15.5,-13.5) AN5(-14.5,-13.5) AN6(-13.5,-13.5) AN7(-12.5,-13.5) AN8(-11.5,-13.5) AN9(-10.5,-13.5) AN10(-9.5,-13.5) AN11(-8.5,-13.5) AN12(-7.5,-13.5) AN13(-6.5,-13.5) AN14(-5.5,-13.5) AN15(-4.5,-13.5) AN16(-3.5,-13.5) AN17(-2.5,-13.5) AN18(-1.5,-13.5) AN19(-0.5,-13.5) AN20(0.5,-13.5) AN21(1.5,-13.5) AN22(2.5,-13.5) AN23(3.5,-13.5) AN24(4.5,-13.5) AN25(5.5,-13.5) AN26(6.5,-13.5) AN27(7.5,-13.5) AN28(8.5,-13.5) AN29(9.5,-13.5) AN30(10.5,-13.5) AN31(11.5,-13.5) AN32(12.5,-13.5) AN33(13.5,-13.5) AN34(14.5,-13.5) AN35(15.5,-13.5) AN36(16.5,-13.5) AN37(17.5,-13.5) AN38(18.5,-13.5) AP1(-18.5,-14.5) AP2(-17.5,-14.5) AP3(-16.5,-14.5) AP4(-15.5,-14.5) AP5(-14.5,-14.5) AP6(-13.5,-14.5) AP7(-12.5,-14.5) AP8(-11.5,-14.5) AP9(-10.5,-14.5) AP10(-9.5,-14.5) AP11(-8.5,-14.5) AP12(-7.5,-14.5) AP13(-6.5,-14.5) AP14(-5.5,-14.5) AP15(-4.5,-14.5) AP16(-3.5,-14.5) AP17(-2.5,-14.5) AP18(-1.5,-14.5) AP19(-0.5,-14.5) AP20(0.5,-14.5) AP21(1.5,-14.5) AP22(2.5,-14.5) AP23(3.5,-14.5) AP24(4.5,-14.5) AP25(5.5,-14.5) AP26(6.5,-14.5) AP27(7.5,-14.5) AP28(8.5,-14.5) AP29(9.5,-14.5) AP30(10.5,-14.5) AP31(11.5,-14.5) AP32(12.5,-14.5) AP33(13.5,-14.5) AP34(14.5,-14.5) AP35(15.5,-14.5) AP36(16.5,-14.5) AP37(17.5,-14.5) AP38(18.5,-14.5) AR1(-18.5,-15.5) AR2(-17.5,-15.5) AR3(-16.5,-15.5) AR4(-15.5,-15.5) AR5(-14.5,-15.5) AR6(-13.5,-15.5) AR7(-12.5,-15.5) AR8(-11.5,-15.5) AR9(-10.5,-15.5) AR10(-9.5,-15.5) AR11(-8.5,-15.5) AR12(-7.5,-15.5) AR13(-6.5,-15.5) AR14(-5.5,-15.5) AR15(-4.5,-15.5) AR16(-3.5,-15.5) AR17(-2.5,-15.5) AR18(-1.5,-15.5) AR19(-0.5,-15.5) AR20(0.5,-15.5) AR21(1.5,-15.5) AR22(2.5,-15.5) AR23(3.5,-15.5) AR24(4.5,-15.5) AR25(5.5,-15.5) AR26(6.5,-15.5) AR27(7.5,-15.5) AR28(8.5,-15.5) AR29(9.5,-15.5) AR30(10.5,-15.5) AR31(11.5,-15.5) AR32(12.5,-15.5) AR33(13.5,-15.5) AR34(14.5,-15.5) AR35(15.5,-15.5) AR36(16.5,-15.5) AR37(17.5,-15.5) AR38(18.5,-15.5) AT1(-18.5,-16.5) AT2(-17.5,-16.5) AT3(-16.5,-16.5) AT4(-15.5,-16.5) AT5(-14.5,-16.5) AT6(-13.5,-16.5) AT7(-12.5,-16.5) AT8(-11.5,-16.5) AT9(-10.5,-16.5) AT10(-9.5,-16.5) AT11(-8.5,-16.5) AT12(-7.5,-16.5) AT13(-6.5,-16.5) AT14(-5.5,-16.5) AT15(-4.5,-16.5) AT16(-3.5,-16.5) AT17(-2.5,-16.5) AT18(-1.5,-16.5) AT19(-0.5,-16.5) AT20(0.5,-16.5) AT21(1.5,-16.5) AT22(2.5,-16.5) AT23(3.5,-16.5) AT24(4.5,-16.5) AT25(5.5,-16.5) AT26(6.5,-16.5) AT27(7.5,-16.5) AT28(8.5,-16.5) AT29(9.5,-16.5) AT30(10.5,-16.5) AT31(11.5,-16.5) AT32(12.5,-16.5) AT33(13.5,-16.5) AT34(14.5,-16.5) AT35(15.5,-16.5) AT36(16.5,-16.5) AT37(17.5,-16.5) AT38(18.5,-16.5) AU1(-18.5,-17.5) AU2(-17.5,-17.5) AU3(-16.5,-17.5) AU4(-15.5,-17.5) AU5(-14.5,-17.5) AU6(-13.5,-17.5) AU7(-12.5,-17.5) AU8(-11.5,-17.5) AU9(-10.5,-17.5) AU10(-9.5,-17.5) AU11(-8.5,-17.5) AU12(-7.5,-17.5) AU13(-6.5,-17.5) AU14(-5.5,-17.5) AU15(-4.5,-17.5) AU16(-3.5,-17.5) AU17(-2.5,-17.5) AU18(-1.5,-17.5) AU19(-0.5,-17.5) AU20(0.5,-17.5) AU21(1.5,-17.5) AU22(2.5,-17.5) AU23(3.5,-17.5) AU24(4.5,-17.5) AU25(5.5,-17.5) AU26(6.5,-17.5) AU27(7.5,-17.5) AU28(8.5,-17.5) AU29(9.5,-17.5) AU30(10.5,-17.5) AU31(11.5,-17.5) AU32(12.5,-17.5) AU33(13.5,-17.5) AU34(14.5,-17.5) AU35(15.5,-17.5) AU36(16.5,-17.5) AU37(17.5,-17.5) AU38(18.5,-17.5) AV1(-18.5,-18.5) AV2(-17.5,-18.5) AV3(-16.5,-18.5) AV4(-15.5,-18.5) AV5(-14.5,-18.5) AV6(-13.5,-18.5) AV7(-12.5,-18.5) AV8(-11.5,-18.5) AV9(-10.5,-18.5) AV10(-9.5,-18.5) AV11(-8.5,-18.5) AV12(-7.5,-18.5) AV13(-6.5,-18.5) AV14(-5.5,-18.5) AV15(-4.5,-18.5) AV16(-3.5,-18.5) AV17(-2.5,-18.5) AV18(-1.5,-18.5) AV19(-0.5,-18.5) AV20(0.5,-18.5) AV21(1.5,-18.5) AV22(2.5,-18.5) AV23(3.5,-18.5) AV24(4.5,-18.5) AV25(5.5,-18.5) AV26(6.5,-18.5) AV27(7.5,-18.5) AV28(8.5,-18.5) AV29(9.5,-18.5) AV30(10.5,-18.5) AV31(11.5,-18.5) AV32(12.5,-18.5) AV33(13.5,-18.5) AV34(14.5,-18.5) AV35(15.5,-18.5) AV36(16.5,-18.5) AV37(17.5,-18.5) AV38(18.5,-18.5) B1(-18.5,17.5) B2(-17.5,17.5) B3(-16.5,17.5) B4(-15.5,17.5) B5(-14.5,17.5) B6(-13.5,17.5) B7(-12.5,17.5) B8(-11.5,17.5) B9(-10.5,17.5) B10(-9.5,17.5) B11(-8.5,17.5) B12(-7.5,17.5) B13(-6.5,17.5) B14(-5.5,17.5) B15(-4.5,17.5) B16(-3.5,17.5) B17(-2.5,17.5) B18(-1.5,17.5) B19(-0.5,17.5) B20(0.5,17.5) B21(1.5,17.5) B22(2.5,17.5) B23(3.5,17.5) B24(4.5,17.5) B25(5.5,17.5) B26(6.5,17.5) B27(7.5,17.5) B28(8.5,17.5) B29(9.5,17.5) B30(10.5,17.5) B31(11.5,17.5) B32(12.5,17.5) B33(13.5,17.5) B34(14.5,17.5) B35(15.5,17.5) B36(16.5,17.5) B37(17.5,17.5) B38(18.5,17.5) C1(-18.5,16.5) C2(-17.5,16.5) C3(-16.5,16.5) C4(-15.5,16.5) C5(-14.5,16.5) C6(-13.5,16.5) C7(-12.5,16.5) C8(-11.5,16.5) C9(-10.5,16.5) C10(-9.5,16.5) C11(-8.5,16.5) C12(-7.5,16.5) C13(-6.5,16.5) C14(-5.5,16.5) C15(-4.5,16.5) C16(-3.5,16.5) C17(-2.5,16.5) C18(-1.5,16.5) C19(-0.5,16.5) C20(0.5,16.5) C21(1.5,16.5) C22(2.5,16.5) C23(3.5,16.5) C24(4.5,16.5) C25(5.5,16.5) C26(6.5,16.5) C27(7.5,16.5) C28(8.5,16.5) C29(9.5,16.5) C30(10.5,16.5) C31(11.5,16.5) C32(12.5,16.5) C33(13.5,16.5) C34(14.5,16.5) C35(15.5,16.5) C36(16.5,16.5) C37(17.5,16.5) C38(18.5,16.5) D1(-18.5,15.5) D2(-17.5,15.5) D3(-16.5,15.5) D4(-15.5,15.5) D5(-14.5,15.5) D6(-13.5,15.5) D7(-12.5,15.5) D8(-11.5,15.5) D9(-10.5,15.5) D10(-9.5,15.5) D11(-8.5,15.5) D12(-7.5,15.5) D13(-6.5,15.5) D14(-5.5,15.5) D15(-4.5,15.5) D16(-3.5,15.5) D17(-2.5,15.5) D18(-1.5,15.5) D19(-0.5,15.5) D20(0.5,15.5) D21(1.5,15.5) D22(2.5,15.5) D23(3.5,15.5) D24(4.5,15.5) D25(5.5,15.5) D26(6.5,15.5) D27(7.5,15.5) D28(8.5,15.5) D29(9.5,15.5) D30(10.5,15.5) D31(11.5,15.5) D32(12.5,15.5) D33(13.5,15.5) D34(14.5,15.5) D35(15.5,15.5) D36(16.5,15.5) D37(17.5,15.5) D38(18.5,15.5) E1(-18.5,14.5) E2(-17.5,14.5) E3(-16.5,14.5) E4(-15.5,14.5) E5(-14.5,14.5) E6(-13.5,14.5) E7(-12.5,14.5) E8(-11.5,14.5) E9(-10.5,14.5) E10(-9.5,14.5) E11(-8.5,14.5) E12(-7.5,14.5) E13(-6.5,14.5) E14(-5.5,14.5) E15(-4.5,14.5) E16(-3.5,14.5) E17(-2.5,14.5) E18(-1.5,14.5) E19(-0.5,14.5) E20(0.5,14.5) E21(1.5,14.5) E22(2.5,14.5) E23(3.5,14.5) E24(4.5,14.5) E25(5.5,14.5) E26(6.5,14.5) E27(7.5,14.5) E28(8.5,14.5) E29(9.5,14.5) E30(10.5,14.5) E31(11.5,14.5) E32(12.5,14.5) E33(13.5,14.5) E34(14.5,14.5) E35(15.5,14.5) E36(16.5,14.5) E37(17.5,14.5) E38(18.5,14.5) F1(-18.5,13.5) F2(-17.5,13.5) F3(-16.5,13.5) F4(-15.5,13.5) F5(-14.5,13.5) F6(-13.5,13.5) F7(-12.5,13.5) F8(-11.5,13.5) F9(-10.5,13.5) F10(-9.5,13.5) F11(-8.5,13.5) F12(-7.5,13.5) F13(-6.5,13.5) F14(-5.5,13.5) F15(-4.5,13.5) F16(-3.5,13.5) F17(-2.5,13.5) F18(-1.5,13.5) F19(-0.5,13.5) F20(0.5,13.5) F21(1.5,13.5) F22(2.5,13.5) F23(3.5,13.5) F24(4.5,13.5) F25(5.5,13.5) F26(6.5,13.5) F27(7.5,13.5) F28(8.5,13.5) F29(9.5,13.5) F30(10.5,13.5) F31(11.5,13.5) F32(12.5,13.5) F33(13.5,13.5) F34(14.5,13.5) F35(15.5,13.5) F36(16.5,13.5) F37(17.5,13.5) F38(18.5,13.5) G1(-18.5,12.5) G2(-17.5,12.5) G3(-16.5,12.5) G4(-15.5,12.5) G5(-14.5,12.5) G6(-13.5,12.5) G7(-12.5,12.5) G8(-11.5,12.5) G9(-10.5,12.5) G10(-9.5,12.5) G11(-8.5,12.5) G12(-7.5,12.5) G13(-6.5,12.5) G14(-5.5,12.5) G15(-4.5,12.5) G16(-3.5,12.5) G17(-2.5,12.5) G18(-1.5,12.5) G19(-0.5,12.5) G20(0.5,12.5) G21(1.5,12.5) G22(2.5,12.5) G23(3.5,12.5) G24(4.5,12.5) G25(5.5,12.5) G26(6.5,12.5) G27(7.5,12.5) G28(8.5,12.5) G29(9.5,12.5) G30(10.5,12.5) G31(11.5,12.5) G32(12.5,12.5) G33(13.5,12.5) G34(14.5,12.5) G35(15.5,12.5) G36(16.5,12.5) G37(17.5,12.5) G38(18.5,12.5) H1(-18.5,11.5) H2(-17.5,11.5) H3(-16.5,11.5) H4(-15.5,11.5) H5(-14.5,11.5) H6(-13.5,11.5) H7(-12.5,11.5) H8(-11.5,11.5) H9(-10.5,11.5) H10(-9.5,11.5) H11(-8.5,11.5) H12(-7.5,11.5) H13(-6.5,11.5) H14(-5.5,11.5) H15(-4.5,11.5) H16(-3.5,11.5) H17(-2.5,11.5) H18(-1.5,11.5) H19(-0.5,11.5) H20(0.5,11.5) H21(1.5,11.5) H22(2.5,11.5) H23(3.5,11.5) H24(4.5,11.5) H25(5.5,11.5) H26(6.5,11.5) H27(7.5,11.5) H28(8.5,11.5) H29(9.5,11.5) H30(10.5,11.5) H31(11.5,11.5) H32(12.5,11.5) H33(13.5,11.5) H34(14.5,11.5) H35(15.5,11.5) H36(16.5,11.5) H37(17.5,11.5) H38(18.5,11.5) J1(-18.5,10.5) J2(-17.5,10.5) J3(-16.5,10.5) J4(-15.5,10.5) J5(-14.5,10.5) J6(-13.5,10.5) J7(-12.5,10.5) J8(-11.5,10.5) J9(-10.5,10.5) J10(-9.5,10.5) J11(-8.5,10.5) J12(-7.5,10.5) J13(-6.5,10.5) J14(-5.5,10.5) J15(-4.5,10.5) J16(-3.5,10.5) J17(-2.5,10.5) J18(-1.5,10.5) J19(-0.5,10.5) J20(0.5,10.5) J21(1.5,10.5) J22(2.5,10.5) J23(3.5,10.5) J24(4.5,10.5) J25(5.5,10.5) J26(6.5,10.5) J27(7.5,10.5) J28(8.5,10.5) J29(9.5,10.5) J30(10.5,10.5) J31(11.5,10.5) J32(12.5,10.5) J33(13.5,10.5) J34(14.5,10.5) J35(15.5,10.5) J36(16.5,10.5) J37(17.5,10.5) J38(18.5,10.5) K1(-18.5,9.5) K2(-17.5,9.5) K3(-16.5,9.5) K4(-15.5,9.5) K5(-14.5,9.5) K6(-13.5,9.5) K7(-12.5,9.5) K8(-11.5,9.5) K9(-10.5,9.5) K10(-9.5,9.5) K11(-8.5,9.5) K12(-7.5,9.5) K13(-6.5,9.5) K14(-5.5,9.5) K15(-4.5,9.5) K16(-3.5,9.5) K17(-2.5,9.5) K18(-1.5,9.5) K19(-0.5,9.5) K20(0.5,9.5) K21(1.5,9.5) K22(2.5,9.5) K23(3.5,9.5) K24(4.5,9.5) K25(5.5,9.5) K26(6.5,9.5) K27(7.5,9.5) K28(8.5,9.5) K29(9.5,9.5) K30(10.5,9.5) K31(11.5,9.5) K32(12.5,9.5) K33(13.5,9.5) K34(14.5,9.5) K35(15.5,9.5) K36(16.5,9.5) K37(17.5,9.5) K38(18.5,9.5) L1(-18.5,8.5) L2(-17.5,8.5) L3(-16.5,8.5) L4(-15.5,8.5) L5(-14.5,8.5) L6(-13.5,8.5) L7(-12.5,8.5) L8(-11.5,8.5) L9(-10.5,8.5) L10(-9.5,8.5) L11(-8.5,8.5) L12(-7.5,8.5) L13(-6.5,8.5) L14(-5.5,8.5) L15(-4.5,8.5) L16(-3.5,8.5) L17(-2.5,8.5) L18(-1.5,8.5) L19(-0.5,8.5) L20(0.5,8.5) L21(1.5,8.5) L22(2.5,8.5) L23(3.5,8.5) L24(4.5,8.5) L25(5.5,8.5) L26(6.5,8.5) L27(7.5,8.5) L28(8.5,8.5) L29(9.5,8.5) L30(10.5,8.5) L31(11.5,8.5) L32(12.5,8.5) L33(13.5,8.5) L34(14.5,8.5) L35(15.5,8.5) L36(16.5,8.5) L37(17.5,8.5) L38(18.5,8.5) M1(-18.5,7.5) M2(-17.5,7.5) M3(-16.5,7.5) M4(-15.5,7.5) M5(-14.5,7.5) M6(-13.5,7.5) M7(-12.5,7.5) M8(-11.5,7.5) M9(-10.5,7.5) M10(-9.5,7.5) M11(-8.5,7.5) M12(-7.5,7.5) M13(-6.5,7.5) M14(-5.5,7.5) M15(-4.5,7.5) M16(-3.5,7.5) M17(-2.5,7.5) M18(-1.5,7.5) M19(-0.5,7.5) M20(0.5,7.5) M21(1.5,7.5) M22(2.5,7.5) M23(3.5,7.5) M24(4.5,7.5) M25(5.5,7.5) M26(6.5,7.5) M27(7.5,7.5) M28(8.5,7.5) M29(9.5,7.5) M30(10.5,7.5) M31(11.5,7.5) M32(12.5,7.5) M33(13.5,7.5) M34(14.5,7.5) M35(15.5,7.5) M36(16.5,7.5) M37(17.5,7.5) M38(18.5,7.5) N1(-18.5,6.5) N2(-17.5,6.5) N3(-16.5,6.5) N4(-15.5,6.5) N5(-14.5,6.5) N6(-13.5,6.5) N7(-12.5,6.5) N8(-11.5,6.5) N9(-10.5,6.5) N10(-9.5,6.5) N11(-8.5,6.5) N12(-7.5,6.5) N13(-6.5,6.5) N14(-5.5,6.5) N15(-4.5,6.5) N16(-3.5,6.5) N17(-2.5,6.5) N18(-1.5,6.5) N19(-0.5,6.5) N20(0.5,6.5) N21(1.5,6.5) N22(2.5,6.5) N23(3.5,6.5) N24(4.5,6.5) N25(5.5,6.5) N26(6.5,6.5) N27(7.5,6.5) N28(8.5,6.5) N29(9.5,6.5) N30(10.5,6.5) N31(11.5,6.5) N32(12.5,6.5) N33(13.5,6.5) N34(14.5,6.5) N35(15.5,6.5) N36(16.5,6.5) N37(17.5,6.5) N38(18.5,6.5) P1(-18.5,5.5) P2(-17.5,5.5) P3(-16.5,5.5) P4(-15.5,5.5) P5(-14.5,5.5) P6(-13.5,5.5) P7(-12.5,5.5) P8(-11.5,5.5) P9(-10.5,5.5) P10(-9.5,5.5) P11(-8.5,5.5) P12(-7.5,5.5) P13(-6.5,5.5) P14(-5.5,5.5) P15(-4.5,5.5) P16(-3.5,5.5) P17(-2.5,5.5) P18(-1.5,5.5) P19(-0.5,5.5) P20(0.5,5.5) P21(1.5,5.5) P22(2.5,5.5) P23(3.5,5.5) P24(4.5,5.5) P25(5.5,5.5) P26(6.5,5.5) P27(7.5,5.5) P28(8.5,5.5) P29(9.5,5.5) P30(10.5,5.5) P31(11.5,5.5) P32(12.5,5.5) P33(13.5,5.5) P34(14.5,5.5) P35(15.5,5.5) P36(16.5,5.5) P37(17.5,5.5) P38(18.5,5.5) R1(-18.5,4.5) R2(-17.5,4.5) R3(-16.5,4.5) R4(-15.5,4.5) R5(-14.5,4.5) R6(-13.5,4.5) R7(-12.5,4.5) R8(-11.5,4.5) R9(-10.5,4.5) R10(-9.5,4.5) R11(-8.5,4.5) R12(-7.5,4.5) R13(-6.5,4.5) R14(-5.5,4.5) R15(-4.5,4.5) R16(-3.5,4.5) R17(-2.5,4.5) R18(-1.5,4.5) R19(-0.5,4.5) R20(0.5,4.5) R21(1.5,4.5) R22(2.5,4.5) R23(3.5,4.5) R24(4.5,4.5) R25(5.5,4.5) R26(6.5,4.5) R27(7.5,4.5) R28(8.5,4.5) R29(9.5,4.5) R30(10.5,4.5) R31(11.5,4.5) R32(12.5,4.5) R33(13.5,4.5) R34(14.5,4.5) R35(15.5,4.5) R36(16.5,4.5) R37(17.5,4.5) R38(18.5,4.5) T1(-18.5,3.5) T2(-17.5,3.5) T3(-16.5,3.5) T4(-15.5,3.5) T5(-14.5,3.5) T6(-13.5,3.5) T7(-12.5,3.5) T8(-11.5,3.5) T9(-10.5,3.5) T10(-9.5,3.5) T11(-8.5,3.5) T12(-7.5,3.5) T13(-6.5,3.5) T14(-5.5,3.5) T15(-4.5,3.5) T16(-3.5,3.5) T17(-2.5,3.5) T18(-1.5,3.5) T19(-0.5,3.5) T20(0.5,3.5) T21(1.5,3.5) T22(2.5,3.5) T23(3.5,3.5) T24(4.5,3.5) T25(5.5,3.5) T26(6.5,3.5) T27(7.5,3.5) T28(8.5,3.5) T29(9.5,3.5) T30(10.5,3.5) T31(11.5,3.5) T32(12.5,3.5) T33(13.5,3.5) T34(14.5,3.5) T35(15.5,3.5) T36(16.5,3.5) T37(17.5,3.5) T38(18.5,3.5) U1(-18.5,2.5) U2(-17.5,2.5) U3(-16.5,2.5) U4(-15.5,2.5) U5(-14.5,2.5) U6(-13.5,2.5) U7(-12.5,2.5) U8(-11.5,2.5) U9(-10.5,2.5) U10(-9.5,2.5) U11(-8.5,2.5) U12(-7.5,2.5) U13(-6.5,2.5) U14(-5.5,2.5) U15(-4.5,2.5) U16(-3.5,2.5) U17(-2.5,2.5) U18(-1.5,2.5) U19(-0.5,2.5) U20(0.5,2.5) U21(1.5,2.5) U22(2.5,2.5) U23(3.5,2.5) U24(4.5,2.5) U25(5.5,2.5) U26(6.5,2.5) U27(7.5,2.5) U28(8.5,2.5) U29(9.5,2.5) U30(10.5,2.5) U31(11.5,2.5) U32(12.5,2.5) U33(13.5,2.5) U34(14.5,2.5) U35(15.5,2.5) U36(16.5,2.5) U37(17.5,2.5) U38(18.5,2.5) V1(-18.5,1.5) V2(-17.5,1.5) V3(-16.5,1.5) V4(-15.5,1.5) V5(-14.5,1.5) V6(-13.5,1.5) V7(-12.5,1.5) V8(-11.5,1.5) V9(-10.5,1.5) V10(-9.5,1.5) V11(-8.5,1.5) V12(-7.5,1.5) V13(-6.5,1.5) V14(-5.5,1.5) V15(-4.5,1.5) V16(-3.5,1.5) V17(-2.5,1.5) V18(-1.5,1.5) V19(-0.5,1.5) V20(0.5,1.5) V21(1.5,1.5) V22(2.5,1.5) V23(3.5,1.5) V24(4.5,1.5) V25(5.5,1.5) V26(6.5,1.5) V27(7.5,1.5) V28(8.5,1.5) V29(9.5,1.5) V30(10.5,1.5) V31(11.5,1.5) V32(12.5,1.5) V33(13.5,1.5) V34(14.5,1.5) V35(15.5,1.5) V36(16.5,1.5) V37(17.5,1.5) V38(18.5,1.5) W1(-18.5,0.5) W2(-17.5,0.5) W3(-16.5,0.5) W4(-15.5,0.5) W5(-14.5,0.5) W6(-13.5,0.5) W7(-12.5,0.5) W8(-11.5,0.5) W9(-10.5,0.5) W10(-9.5,0.5) W11(-8.5,0.5) W12(-7.5,0.5) W13(-6.5,0.5) W14(-5.5,0.5) W15(-4.5,0.5) W16(-3.5,0.5) W17(-2.5,0.5) W18(-1.5,0.5) W19(-0.5,0.5) W20(0.5,0.5) W21(1.5,0.5) W22(2.5,0.5) W23(3.5,0.5) W24(4.5,0.5) W25(5.5,0.5) W26(6.5,0.5) W27(7.5,0.5) W28(8.5,0.5) W29(9.5,0.5) W30(10.5,0.5) W31(11.5,0.5) W32(12.5,0.5) W33(13.5,0.5) W34(14.5,0.5) W35(15.5,0.5) W36(16.5,0.5) W37(17.5,0.5) W38(18.5,0.5) Y1(-18.5,-0.5) Y2(-17.5,-0.5) Y3(-16.5,-0.5) Y4(-15.5,-0.5) Y5(-14.5,-0.5) Y6(-13.5,-0.5) Y7(-12.5,-0.5) Y8(-11.5,-0.5) Y9(-10.5,-0.5) Y10(-9.5,-0.5) Y11(-8.5,-0.5) Y12(-7.5,-0.5) Y13(-6.5,-0.5) Y14(-5.5,-0.5) Y15(-4.5,-0.5) Y16(-3.5,-0.5) Y17(-2.5,-0.5) Y18(-1.5,-0.5) Y19(-0.5,-0.5) Y20(0.5,-0.5) Y21(1.5,-0.5) Y22(2.5,-0.5) Y23(3.5,-0.5) Y24(4.5,-0.5) Y25(5.5,-0.5) Y26(6.5,-0.5) Y27(7.5,-0.5) Y28(8.5,-0.5) Y29(9.5,-0.5) Y30(10.5,-0.5) Y31(11.5,-0.5) Y32(12.5,-0.5) Y33(13.5,-0.5) Y34(14.5,-0.5) Y35(15.5,-0.5) Y36(16.5,-0.5) Y37(17.5,-0.5) Y38(18.5,-0.5)
Top Overlay:
  circle w0.25: c-20.65,18.5 r0.125
  region: -19,20 -20,19 -20,20
  lines w0.2: -20,19 -19,20 ; -20,-20 -20,20 20,20 20,-20 -20,-20
Mechanical 13:
  lines w0.1: -20,-20 -20,20 20,20 20,-20 -20,-20
Mechanical 15:
  lines w0.1: -0.5,0 0.5,0 ; 0,-0.5 0,0.5 ; -21,-21 -21,21 21,21 21,-21 -21,-21
3D body: height 0, standoff 0, extent -20,-20 20,20

## BGA100P39X39-680 [mm] "680-Ball Fine Pitch Ball Grid Array (FG680)"
height 1.7
pads (680):
  round 0.5 smd: A1(-19,19) A2(-18,19) A3(-17,19) A4(-16,19) A5(-15,19) A6(-14,19) A7(-13,19) A8(-12,19) A9(-11,19) A10(-10,19) A11(-9,19) A12(-8,19) A13(-7,19) A14(-6,19) A15(-5,19) A16(-4,19) A17(-3,19) A18(-2,19) A19(-1,19) A20(0,19) A21(1,19) A22(2,19) A23(3,19) A24(4,19) A25(5,19) A26(6,19) A27(7,19) A28(8,19) A29(9,19) A30(10,19) A31(11,19) A32(12,19) A33(13,19) A34(14,19) A35(15,19) A36(16,19) A37(17,19) A38(18,19) A39(19,19) AA1(-19,-1) AA2(-18,-1) AA3(-17,-1) AA4(-16,-1) AA5(-15,-1) AA35(15,-1) AA36(16,-1) AA37(17,-1) AA38(18,-1) AA39(19,-1) AB1(-19,-2) AB2(-18,-2) AB3(-17,-2) AB4(-16,-2) AB5(-15,-2) AB35(15,-2) AB36(16,-2) AB37(17,-2) AB38(18,-2) AB39(19,-2) AC1(-19,-3) AC2(-18,-3) AC3(-17,-3) AC4(-16,-3) AC5(-15,-3) AC35(15,-3) AC36(16,-3) AC37(17,-3) AC38(18,-3) AC39(19,-3) AD1(-19,-4) AD2(-18,-4) AD3(-17,-4) AD4(-16,-4) AD5(-15,-4) AD35(15,-4) AD36(16,-4) AD37(17,-4) AD38(18,-4) AD39(19,-4) AE1(-19,-5) AE2(-18,-5) AE3(-17,-5) AE4(-16,-5) AE5(-15,-5) AE35(15,-5) AE36(16,-5) AE37(17,-5) AE38(18,-5) AE39(19,-5) AF1(-19,-6) AF2(-18,-6) AF3(-17,-6) AF4(-16,-6) AF5(-15,-6) AF35(15,-6) AF36(16,-6) AF37(17,-6) AF38(18,-6) AF39(19,-6) AG1(-19,-7) AG2(-18,-7) AG3(-17,-7) AG4(-16,-7) AG5(-15,-7) AG35(15,-7) AG36(16,-7) AG37(17,-7) AG38(18,-7) AG39(19,-7) AH1(-19,-8) AH2(-18,-8) AH3(-17,-8) AH4(-16,-8) AH5(-15,-8) AH35(15,-8) AH36(16,-8) AH37(17,-8) AH38(18,-8) AH39(19,-8) AJ1(-19,-9) AJ2(-18,-9) AJ3(-17,-9) AJ4(-16,-9) AJ5(-15,-9) AJ35(15,-9) AJ36(16,-9) AJ37(17,-9) AJ38(18,-9) AJ39(19,-9) AK1(-19,-10) AK2(-18,-10) AK3(-17,-10) AK4(-16,-10) AK5(-15,-10) AK35(15,-10) AK36(16,-10) AK37(17,-10) AK38(18,-10) AK39(19,-10) AL1(-19,-11) AL2(-18,-11) AL3(-17,-11) AL4(-16,-11) AL5(-15,-11) AL35(15,-11) AL36(16,-11) AL37(17,-11) AL38(18,-11) AL39(19,-11) AM1(-19,-12) AM2(-18,-12) AM3(-17,-12) AM4(-16,-12) AM5(-15,-12) AM35(15,-12) AM36(16,-12) AM37(17,-12) AM38(18,-12) AM39(19,-12) AN1(-19,-13) AN2(-18,-13) AN3(-17,-13) AN4(-16,-13) AN5(-15,-13) AN35(15,-13) AN36(16,-13) AN37(17,-13) AN38(18,-13) AN39(19,-13) AP1(-19,-14) AP2(-18,-14) AP3(-17,-14) AP4(-16,-14) AP5(-15,-14) AP35(15,-14) AP36(16,-14) AP37(17,-14) AP38(18,-14) AP39(19,-14) AR1(-19,-15) AR2(-18,-15) AR3(-17,-15) AR4(-16,-15) AR5(-15,-15) AR6(-14,-15) AR7(-13,-15) AR8(-12,-15) AR9(-11,-15) AR10(-10,-15) AR11(-9,-15) AR12(-8,-15) AR13(-7,-15) AR14(-6,-15) AR15(-5,-15) AR16(-4,-15) AR17(-3,-15) AR18(-2,-15) AR19(-1,-15) AR20(0,-15) AR21(1,-15) AR22(2,-15) AR23(3,-15) AR24(4,-15) AR25(5,-15) AR26(6,-15) AR27(7,-15) AR28(8,-15) AR29(9,-15) AR30(10,-15) AR31(11,-15) AR32(12,-15) AR33(13,-15) AR34(14,-15) AR35(15,-15) AR36(16,-15) AR37(17,-15) AR38(18,-15) AR39(19,-15) AT1(-19,-16) AT2(-18,-16) AT3(-17,-16) AT4(-16,-16) AT5(-15,-16) AT6(-14,-16) AT7(-13,-16) AT8(-12,-16) AT9(-11,-16) AT10(-10,-16) AT11(-9,-16) AT12(-8,-16) AT13(-7,-16) AT14(-6,-16) AT15(-5,-16) AT16(-4,-16) AT17(-3,-16) AT18(-2,-16) AT19(-1,-16) AT20(0,-16) AT21(1,-16) AT22(2,-16) AT23(3,-16) AT24(4,-16) AT25(5,-16) AT26(6,-16) AT27(7,-16) AT28(8,-16) AT29(9,-16) AT30(10,-16) AT31(11,-16) AT32(12,-16) AT33(13,-16) AT34(14,-16) AT35(15,-16) AT36(16,-16) AT37(17,-16) AT38(18,-16) AT39(19,-16) AU1(-19,-17) AU2(-18,-17) AU3(-17,-17) AU4(-16,-17) AU5(-15,-17) AU6(-14,-17) AU7(-13,-17) AU8(-12,-17) AU9(-11,-17) AU10(-10,-17) AU11(-9,-17) AU12(-8,-17) AU13(-7,-17) AU14(-6,-17) AU15(-5,-17) AU16(-4,-17) AU17(-3,-17) AU18(-2,-17) AU19(-1,-17) AU20(0,-17) AU21(1,-17) AU22(2,-17) AU23(3,-17) AU24(4,-17) AU25(5,-17) AU26(6,-17) AU27(7,-17) AU28(8,-17) AU29(9,-17) AU30(10,-17) AU31(11,-17) AU32(12,-17) AU33(13,-17) AU34(14,-17) AU35(15,-17) AU36(16,-17) AU37(17,-17) AU38(18,-17) AU39(19,-17) AV1(-19,-18) AV2(-18,-18) AV3(-17,-18) AV4(-16,-18) AV5(-15,-18) AV6(-14,-18) AV7(-13,-18) AV8(-12,-18) AV9(-11,-18) AV10(-10,-18) AV11(-9,-18) AV12(-8,-18) AV13(-7,-18) AV14(-6,-18) AV15(-5,-18) AV16(-4,-18) AV17(-3,-18) AV18(-2,-18) AV19(-1,-18) AV20(0,-18) AV21(1,-18) AV22(2,-18) AV23(3,-18) AV24(4,-18) AV25(5,-18) AV26(6,-18) AV27(7,-18) AV28(8,-18) AV29(9,-18) AV30(10,-18) AV31(11,-18) AV32(12,-18) AV33(13,-18) AV34(14,-18) AV35(15,-18) AV36(16,-18) AV37(17,-18) AV38(18,-18) AV39(19,-18) AW1(-19,-19) AW2(-18,-19) AW3(-17,-19) AW4(-16,-19) AW5(-15,-19) AW6(-14,-19) AW7(-13,-19) AW8(-12,-19) AW9(-11,-19) AW10(-10,-19) AW11(-9,-19) AW12(-8,-19) AW13(-7,-19) AW14(-6,-19) AW15(-5,-19) AW16(-4,-19) AW17(-3,-19) AW18(-2,-19) AW19(-1,-19) AW20(0,-19) AW21(1,-19) AW22(2,-19) AW23(3,-19) AW24(4,-19) AW25(5,-19) AW26(6,-19) AW27(7,-19) AW28(8,-19) AW29(9,-19) AW30(10,-19) AW31(11,-19) AW32(12,-19) AW33(13,-19) AW34(14,-19) AW35(15,-19) AW36(16,-19) AW37(17,-19) AW38(18,-19) AW39(19,-19) B1(-19,18) B2(-18,18) B3(-17,18) B4(-16,18) B5(-15,18) B6(-14,18) B7(-13,18) B8(-12,18) B9(-11,18) B10(-10,18) B11(-9,18) B12(-8,18) B13(-7,18) B14(-6,18) B15(-5,18) B16(-4,18) B17(-3,18) B18(-2,18) B19(-1,18) B20(0,18) B21(1,18) B22(2,18) B23(3,18) B24(4,18) B25(5,18) B26(6,18) B27(7,18) B28(8,18) B29(9,18) B30(10,18) B31(11,18) B32(12,18) B33(13,18) B34(14,18) B35(15,18) B36(16,18) B37(17,18) B38(18,18) B39(19,18) C1(-19,17) C2(-18,17) C3(-17,17) C4(-16,17) C5(-15,17) C6(-14,17) C7(-13,17) C8(-12,17) C9(-11,17) C10(-10,17) C11(-9,17) C12(-8,17) C13(-7,17) C14(-6,17) C15(-5,17) C16(-4,17) C17(-3,17) C18(-2,17) C19(-1,17) C20(0,17) C21(1,17) C22(2,17) C23(3,17) C24(4,17) C25(5,17) C26(6,17) C27(7,17) C28(8,17) C29(9,17) C30(10,17) C31(11,17) C32(12,17) C33(13,17) C34(14,17) C35(15,17) C36(16,17) C37(17,17) C38(18,17) C39(19,17) D1(-19,16) D2(-18,16) D3(-17,16) D4(-16,16) D5(-15,16) D6(-14,16) D7(-13,16) D8(-12,16) D9(-11,16) D10(-10,16) D11(-9,16) D12(-8,16) D13(-7,16) D14(-6,16) D15(-5,16) D16(-4,16) D17(-3,16) D18(-2,16) D19(-1,16) D20(0,16) D21(1,16) D22(2,16) D23(3,16) D24(4,16) D25(5,16) D26(6,16) D27(7,16) D28(8,16) D29(9,16) D30(10,16) D31(11,16) D32(12,16) D33(13,16) D34(14,16) D35(15,16) D36(16,16) D37(17,16) D38(18,16) D39(19,16) E1(-19,15) E2(-18,15) E3(-17,15) E4(-16,15) E5(-15,15) E6(-14,15) E7(-13,15) E8(-12,15) E9(-11,15) E10(-10,15) E11(-9,15) E12(-8,15) E13(-7,15) E14(-6,15) E15(-5,15) E16(-4,15) E17(-3,15) E18(-2,15) E19(-1,15) E20(0,15) E21(1,15) E22(2,15) E23(3,15) E24(4,15) E25(5,15) E26(6,15) E27(7,15) E28(8,15) E29(9,15) E30(10,15) E31(11,15) E32(12,15) E33(13,15) E34(14,15) E35(15,15) E36(16,15) E37(17,15) E38(18,15) E39(19,15) F1(-19,14) F2(-18,14) F3(-17,14) F4(-16,14) F5(-15,14) F35(15,14) F36(16,14) F37(17,14) F38(18,14) F39(19,14) G1(-19,13) G2(-18,13) G3(-17,13) G4(-16,13) G5(-15,13) G35(15,13) G36(16,13) G37(17,13) G38(18,13) G39(19,13) H1(-19,12) H2(-18,12) H3(-17,12) H4(-16,12) H5(-15,12) H35(15,12) H36(16,12) H37(17,12) H38(18,12) H39(19,12) J1(-19,11) J2(-18,11) J3(-17,11) J4(-16,11) J5(-15,11) J35(15,11) J36(16,11) J37(17,11) J38(18,11) J39(19,11) K1(-19,10) K2(-18,10) K3(-17,10) K4(-16,10) K5(-15,10) K35(15,10) K36(16,10) K37(17,10) K38(18,10) K39(19,10) L1(-19,9) L2(-18,9) L3(-17,9) L4(-16,9) L5(-15,9) L35(15,9) L36(16,9) L37(17,9) L38(18,9) L39(19,9) M1(-19,8) M2(-18,8) M3(-17,8) M4(-16,8) M5(-15,8) M35(15,8) M36(16,8) M37(17,8) M38(18,8) M39(19,8) N1(-19,7) N2(-18,7) N3(-17,7) N4(-16,7) N5(-15,7) N35(15,7) N36(16,7) N37(17,7) N38(18,7) N39(19,7) P1(-19,6) P2(-18,6) P3(-17,6) P4(-16,6) P5(-15,6) P35(15,6) P36(16,6) P37(17,6) P38(18,6) P39(19,6) R1(-19,5) R2(-18,5) R3(-17,5) R4(-16,5) R5(-15,5) R35(15,5) R36(16,5) R37(17,5) R38(18,5) R39(19,5) T1(-19,4) T2(-18,4) T3(-17,4) T4(-16,4) T5(-15,4) T35(15,4) T36(16,4) T37(17,4) T38(18,4) T39(19,4) U1(-19,3) U2(-18,3) U3(-17,3) U4(-16,3) U5(-15,3) U35(15,3) U36(16,3) U37(17,3) U38(18,3) U39(19,3) V1(-19,2) V2(-18,2) V3(-17,2) V4(-16,2) V5(-15,2) V35(15,2) V36(16,2) V37(17,2) V38(18,2) V39(19,2) W1(-19,1) W2(-18,1) W3(-17,1) W4(-16,1) W5(-15,1) W35(15,1) W36(16,1) W37(17,1) W38(18,1) W39(19,1) Y1(-19,0) Y2(-18,0) Y3(-17,0) Y4(-16,0) Y5(-15,0) Y35(15,0) Y36(16,0) Y37(17,0) Y38(18,0) Y39(19,0)
Top Overlay:
  circle w0.25: c-20.65,19 r0.125
  region: -19,20 -20,19 -20,20
  lines w0.2: -20,19 -19,20 ; -20,-20 20,-20 20,20 -20,20 -20,-20
Mechanical 13:
  lines w0.1: -20,-20 20,-20 20,20 -20,20 -20,-20
Mechanical 15:
  lines w0.1: -0.5,0 0.5,0 ; 0,-0.5 0,0.5 ; -21,-21 21,-21 21,21 -21,21 -21,-21
3D body: height 0, standoff 0, extent -20,-20 20,20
